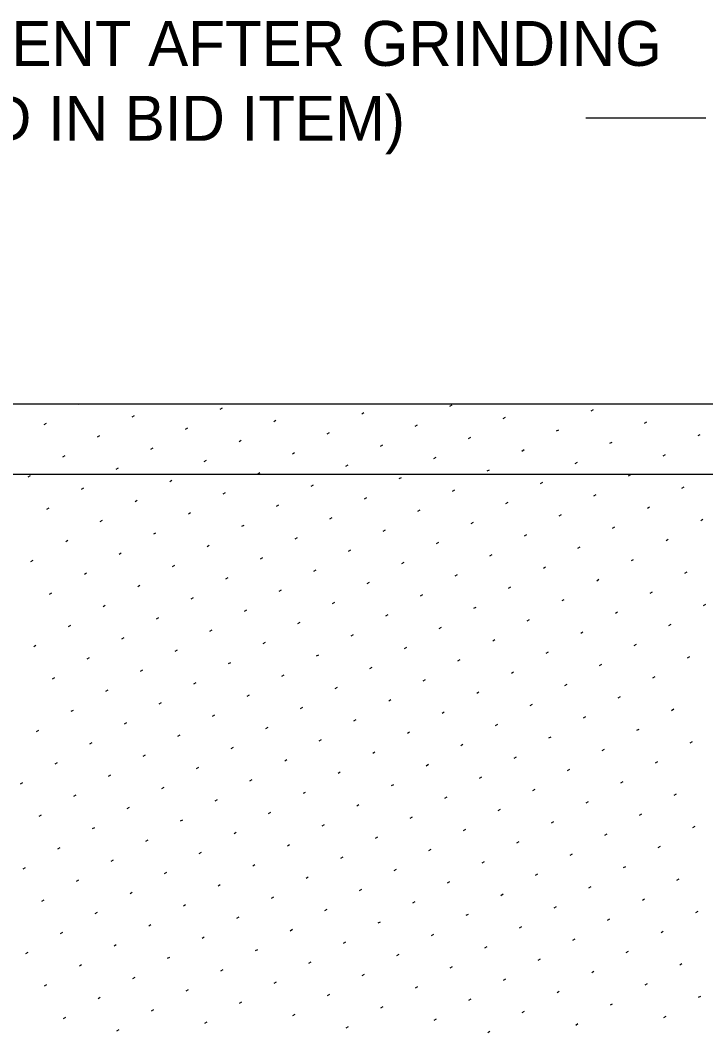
# Model space of a CAD drawing. Extents: x 49991.4 to 50021, y 49987.6 to 50011.4.
# Drawn here: x 50003.173 to 50004.089, y 49994.036 to 49995.39 of the extents above; entities that cross this region are included whole.
import ezdxf

# ---------------------------------------------------------------- set-up
doc = ezdxf.new("R2010")
doc.units = 0
for name, color, linetype in [('Level 1', 7, 'Continuous'), ('Level 2', 7, 'Continuous'), ('Level 3', 7, 'Continuous')]:
    doc.layers.add(name, color=color, linetype=linetype)

msp = doc.modelspace()

# ---------------------------------------------------------------- linework, layer by layer
at = {"layer": 'Level 1'}
for p, q in [((50002.5376, 49994.8772), (50004.5362, 49994.8772)), ((50008.0315, 49994.7828), (50001.9803, 49994.7828))]:
    msp.add_line(p, q, dxfattribs=at)
msp.add_ellipse((50004.6259, 49996.2377), major_axis=(0, -2.952), ratio=0.83118, start_param=5.208402, end_param=6.283185, dxfattribs=at)
at = {"layer": 'Level 3'}
for p, q in [((50004.0891, 49995.2588), (50003.9291, 49995.2588)), ((50003.2514, 49994.8768), (50003.2521, 49994.8772)), ((50003.4404, 49994.8704), (50003.4434, 49994.8722)), ((50003.6294, 49994.8641), (50003.6324, 49994.8658)), ((50003.7471, 49994.8743), (50003.7501, 49994.876)), ((50003.9361, 49994.868), (50003.9391, 49994.8697)), ((50003.205, 49994.85), (50003.208, 49994.8518)), ((50003.3227, 49994.8602), (50003.3257, 49994.862)), ((50003.5117, 49994.8539), (50003.5147, 49994.8556)), ((50003.8184, 49994.8577), (50003.8214, 49994.8595)), ((50004.0074, 49994.8514), (50004.0104, 49994.8532)), ((50003.394, 49994.8437), (50003.3971, 49994.8454)), ((50003.583, 49994.8373), (50003.5861, 49994.8391)), ((50003.7007, 49994.8475), (50003.7038, 49994.8493)), ((50003.8897, 49994.8412), (50003.8928, 49994.8429)), ((50004.0788, 49994.8349), (50004.0818, 49994.8366)), ((50003.2764, 49994.8335), (50003.2794, 49994.8352)), ((50003.4654, 49994.8271), (50003.4684, 49994.8289)), ((50003.7721, 49994.831), (50003.7751, 49994.8327)), ((50003.9611, 49994.8247), (50003.9641, 49994.8264)), ((50003.3477, 49994.8169), (50003.3507, 49994.8187)), ((50003.5367, 49994.8106), (50003.5397, 49994.8123)), ((50003.6544, 49994.8208), (50003.6574, 49994.8225)), ((50003.8434, 49994.8144), (50003.8464, 49994.8162)), ((50004.0324, 49994.8081), (50004.0354, 49994.8099)), ((50003.23, 49994.8067), (50003.233, 49994.8085)), ((50003.419, 49994.8004), (50003.4221, 49994.8021)), ((50003.608, 49994.794), (50003.6111, 49994.7958)), ((50003.7257, 49994.8042), (50003.7288, 49994.806)), ((50003.9147, 49994.7979), (50003.9178, 49994.7996)), ((50003.3014, 49994.7902), (50003.3044, 49994.7919)), ((50003.4904, 49994.7838), (50003.4934, 49994.7856)), ((50003.7971, 49994.7877), (50003.8001, 49994.7894)), ((50003.9861, 49994.7814), (50003.9891, 49994.7831)), ((50003.1837, 49994.78), (50003.1867, 49994.7817)), ((50003.3727, 49994.7736), (50003.3757, 49994.7754)), ((50003.5617, 49994.7673), (50003.5647, 49994.769)), ((50003.6794, 49994.7775), (50003.6824, 49994.7792)), ((50003.8684, 49994.7711), (50003.8714, 49994.7729)), ((50003.255, 49994.7634), (50003.258, 49994.7652)), ((50003.444, 49994.7571), (50003.4471, 49994.7588)), ((50003.7507, 49994.7609), (50003.7538, 49994.7627)), ((50003.9397, 49994.7546), (50003.9428, 49994.7563)), ((50004.0574, 49994.7648), (50004.0604, 49994.7666)), ((50003.3264, 49994.7469), (50003.3294, 49994.7486)), ((50003.5154, 49994.7405), (50003.5184, 49994.7423)), ((50003.633, 49994.7507), (50003.6361, 49994.7525)), ((50003.8221, 49994.7444), (50003.8251, 49994.7461)), ((50003.2087, 49994.7367), (50003.2117, 49994.7384)), ((50003.3977, 49994.7303), (50003.4007, 49994.7321)), ((50003.7044, 49994.7342), (50003.7074, 49994.7359)), ((50003.8934, 49994.7278), (50003.8964, 49994.7296)), ((50004.0111, 49994.738), (50004.0141, 49994.7398)), ((50003.28, 49994.7201), (50003.283, 49994.7219)), ((50003.469, 49994.7138), (50003.4721, 49994.7155)), ((50003.5867, 49994.724), (50003.5897, 49994.7257)), ((50003.7757, 49994.7176), (50003.7788, 49994.7194)), ((50004.0824, 49994.7215), (50004.0854, 49994.7233)), ((50003.3514, 49994.7036), (50003.3544, 49994.7053)), ((50003.658, 49994.7074), (50003.6611, 49994.7092)), ((50003.8471, 49994.7011), (50003.8501, 49994.7028)), ((50003.9647, 49994.7113), (50003.9678, 49994.713)), ((50003.2337, 49994.6934), (50003.2367, 49994.6951)), ((50003.4227, 49994.687), (50003.4257, 49994.6888)), ((50003.5404, 49994.6972), (50003.5434, 49994.699)), ((50003.7294, 49994.6909), (50003.7324, 49994.6926)), ((50004.0361, 49994.6947), (50004.0391, 49994.6965)), ((50003.305, 49994.6768), (50003.308, 49994.6786)), ((50003.6117, 49994.6807), (50003.6147, 49994.6824)), ((50003.8007, 49994.6743), (50003.8038, 49994.6761)), ((50003.9184, 49994.6845), (50003.9214, 49994.6863)), ((50003.1873, 49994.6666), (50003.1904, 49994.6684)), ((50003.3764, 49994.6603), (50003.3794, 49994.662)), ((50003.494, 49994.6705), (50003.4971, 49994.6722)), ((50003.683, 49994.6641), (50003.6861, 49994.6659)), ((50003.9897, 49994.668), (50003.9928, 49994.6697)), ((50003.2587, 49994.6501), (50003.2617, 49994.6518)), ((50003.5654, 49994.6539), (50003.5684, 49994.6557)), ((50003.7544, 49994.6476), (50003.7574, 49994.6493)), ((50003.8721, 49994.6578), (50003.8751, 49994.6595)), ((50004.0611, 49994.6514), (50004.0641, 49994.6532)), ((50003.33, 49994.6335), (50003.333, 49994.6353)), ((50003.4477, 49994.6437), (50003.4507, 49994.6455)), ((50003.6367, 49994.6374), (50003.6397, 49994.6391)), ((50003.9434, 49994.6412), (50003.9464, 49994.643)), ((50003.2123, 49994.6233), (50003.2154, 49994.6251)), ((50003.519, 49994.6272), (50003.5221, 49994.6289)), ((50003.708, 49994.6208), (50003.7111, 49994.6226)), ((50003.8257, 49994.631), (50003.8288, 49994.6328)), ((50004.0147, 49994.6247), (50004.0178, 49994.6264)), ((50003.2837, 49994.6068), (50003.2867, 49994.6085)), ((50003.4014, 49994.617), (50003.4044, 49994.6187)), ((50003.5904, 49994.6106), (50003.5934, 49994.6124)), ((50003.8971, 49994.6145), (50003.9001, 49994.6162)), ((50004.0861, 49994.6081), (50004.0891, 49994.6099)), ((50003.4727, 49994.6004), (50003.4757, 49994.6022)), ((50003.6617, 49994.5941), (50003.6647, 49994.5958)), ((50003.7794, 49994.6043), (50003.7824, 49994.606)), ((50003.9684, 49994.5979), (50003.9714, 49994.5997)), ((50003.2373, 49994.58), (50003.2404, 49994.5818)), ((50003.355, 49994.5902), (50003.358, 49994.592)), ((50003.544, 49994.5839), (50003.5471, 49994.5856)), ((50003.733, 49994.5775), (50003.7361, 49994.5793)), ((50003.8507, 49994.5877), (50003.8538, 49994.5895)), ((50004.0397, 49994.5814), (50004.0428, 49994.5831)), ((50003.4264, 49994.5737), (50003.4294, 49994.5754)), ((50003.6154, 49994.5673), (50003.6184, 49994.5691)), ((50003.9221, 49994.5712), (50003.9251, 49994.5729)), ((50003.191, 49994.5533), (50003.194, 49994.555)), ((50003.3087, 49994.5635), (50003.3117, 49994.5652)), ((50003.4977, 49994.5571), (50003.5007, 49994.5589)), ((50003.6867, 49994.5508), (50003.6897, 49994.5525)), ((50003.8044, 49994.561), (50003.8074, 49994.5627)), ((50003.9934, 49994.5546), (50003.9964, 49994.5564)), ((50003.2623, 49994.5367), (50003.2654, 49994.5385)), ((50003.38, 49994.5469), (50003.383, 49994.5487)), ((50003.569, 49994.5406), (50003.5721, 49994.5423)), ((50003.8757, 49994.5444), (50003.8788, 49994.5462)), ((50004.0647, 49994.5381), (50004.0678, 49994.5398)), ((50003.4514, 49994.5304), (50003.4544, 49994.5321)), ((50003.6404, 49994.524), (50003.6434, 49994.5258)), ((50003.758, 49994.5342), (50003.7611, 49994.536)), ((50003.9471, 49994.5279), (50003.9501, 49994.5296)), ((50003.216, 49994.51), (50003.219, 49994.5117)), ((50003.3337, 49994.5202), (50003.3367, 49994.5219)), ((50003.5227, 49994.5138), (50003.5257, 49994.5156)), ((50003.8294, 49994.5177), (50003.8324, 49994.5194)), ((50004.0184, 49994.5113), (50004.0214, 49994.5131)), ((50003.405, 49994.5036), (50003.408, 49994.5054)), ((50003.594, 49994.4973), (50003.5971, 49994.499)), ((50003.7117, 49994.5075), (50003.7147, 49994.5092)), ((50003.9007, 49994.5011), (50003.9038, 49994.5029)), ((50003.2873, 49994.4934), (50003.2904, 49994.4952)), ((50003.4764, 49994.4871), (50003.4794, 49994.4888)), ((50003.783, 49994.4909), (50003.7861, 49994.4927)), ((50003.9721, 49994.4846), (50003.9751, 49994.4863)), ((50003.3587, 49994.4769), (50003.3617, 49994.4786)), ((50003.5477, 49994.4705), (50003.5507, 49994.4723)), ((50003.6654, 49994.4807), (50003.6684, 49994.4825)), ((50003.8544, 49994.4744), (50003.8574, 49994.4761)), ((50003.241, 49994.4667), (50003.244, 49994.4684)), ((50003.43, 49994.4603), (50003.433, 49994.4621)), ((50003.7367, 49994.4642), (50003.7397, 49994.4659)), ((50003.9257, 49994.4578), (50003.9288, 49994.4596)), ((50004.0434, 49994.468), (50004.0464, 49994.4698)), ((50003.3123, 49994.4501), (50003.3154, 49994.4519)), ((50003.5014, 49994.4438), (50003.5044, 49994.4455)), ((50003.619, 49994.454), (50003.6221, 49994.4557)), ((50003.808, 49994.4476), (50003.8111, 49994.4494)), ((50003.1947, 49994.4399), (50003.1977, 49994.4416)), ((50003.3837, 49994.4336), (50003.3867, 49994.4353)), ((50003.6904, 49994.4374), (50003.6934, 49994.4392)), ((50003.8794, 49994.4311), (50003.8824, 49994.4328)), ((50003.9971, 49994.4413), (50004.0001, 49994.443)), ((50003.266, 49994.4233), (50003.269, 49994.4251)), ((50003.455, 49994.417), (50003.458, 49994.4188)), ((50003.5727, 49994.4272), (50003.5757, 49994.429)), ((50003.7617, 49994.4209), (50003.7647, 49994.4226)), ((50004.0684, 49994.4247), (50004.0714, 49994.4265)), ((50003.3373, 49994.4068), (50003.3404, 49994.4086)), ((50003.644, 49994.4107), (50003.6471, 49994.4124)), ((50003.833, 49994.4043), (50003.8361, 49994.4061)), ((50003.9507, 49994.4145), (50003.9538, 49994.4163)), ((50003.2197, 49994.3966), (50003.2227, 49994.3983)), ((50003.4087, 49994.3903), (50003.4117, 49994.392)), ((50003.5264, 49994.4005), (50003.5294, 49994.4022)), ((50003.7154, 49994.3941), (50003.7184, 49994.3959)), ((50004.0221, 49994.398), (50004.0251, 49994.3997)), ((50003.291, 49994.38), (50003.294, 49994.3818)), ((50003.5977, 49994.3839), (50003.6007, 49994.3857)), ((50003.7867, 49994.3776), (50003.7897, 49994.3793)), ((50003.9044, 49994.3878), (50003.9074, 49994.3895)), ((50003.1733, 49994.3698), (50003.1764, 49994.3716)), ((50003.3623, 49994.3635), (50003.3654, 49994.3653)), ((50003.48, 49994.3737), (50003.483, 49994.3755)), ((50003.669, 49994.3674), (50003.6721, 49994.3691)), ((50003.858, 49994.361), (50003.8611, 49994.3628)), ((50003.9757, 49994.3712), (50003.9788, 49994.373)), ((50003.2447, 49994.3533), (50003.2477, 49994.355)), ((50003.5514, 49994.3572), (50003.5544, 49994.3589)), ((50003.7404, 49994.3508), (50003.7434, 49994.3526)), ((50004.0471, 49994.3547), (50004.0501, 49994.3564)), ((50003.316, 49994.3367), (50003.319, 49994.3385)), ((50003.4337, 49994.347), (50003.4367, 49994.3487)), ((50003.6227, 49994.3406), (50003.6257, 49994.3424)), ((50003.8117, 49994.3343), (50003.8147, 49994.336)), ((50003.9294, 49994.3445), (50003.9324, 49994.3462)), ((50003.1983, 49994.3265), (50003.2014, 49994.3283)), ((50003.3873, 49994.3202), (50003.3904, 49994.3219)), ((50003.505, 49994.3304), (50003.508, 49994.3322)), ((50003.694, 49994.3241), (50003.6971, 49994.3258)), ((50004.0007, 49994.3279), (50004.0038, 49994.3297)), ((50003.2697, 49994.31), (50003.2727, 49994.3117)), ((50003.5764, 49994.3139), (50003.5794, 49994.3156)), ((50003.7654, 49994.3075), (50003.7684, 49994.3093)), ((50003.883, 49994.3177), (50003.8861, 49994.3195)), ((50004.0721, 49994.3114), (50004.0751, 49994.3131)), ((50003.341, 49994.2934), (50003.344, 49994.2952)), ((50003.4587, 49994.3037), (50003.4617, 49994.3054)), ((50003.6477, 49994.2973), (50003.6507, 49994.2991)), ((50003.9544, 49994.3012), (50003.9574, 49994.3029)), ((50003.2233, 49994.2832), (50003.2264, 49994.285)), ((50003.53, 49994.2871), (50003.533, 49994.2889)), ((50003.719, 49994.2808), (50003.7221, 49994.2825)), ((50003.8367, 49994.291), (50003.8397, 49994.2927)), ((50004.0257, 49994.2846), (50004.0288, 49994.2864)), ((50003.2947, 49994.2667), (50003.2977, 49994.2684)), ((50003.4123, 49994.2769), (50003.4154, 49994.2786)), ((50003.6014, 49994.2706), (50003.6044, 49994.2723)), ((50003.908, 49994.2744), (50003.9111, 49994.2762)), ((50003.177, 49994.2565), (50003.18, 49994.2582)), ((50003.4837, 49994.2603), (50003.4867, 49994.2621)), ((50003.6727, 49994.254), (50003.6757, 49994.2558)), ((50003.7904, 49994.2642), (50003.7934, 49994.266)), ((50003.9794, 49994.2579), (50003.9824, 49994.2596)), ((50003.2483, 49994.2399), (50003.2514, 49994.2417)), ((50003.366, 49994.2501), (50003.369, 49994.2519)), ((50003.555, 49994.2438), (50003.558, 49994.2456)), ((50003.8617, 49994.2477), (50003.8647, 49994.2494)), ((50004.0507, 49994.2413), (50004.0538, 49994.2431)), ((50003.4373, 49994.2336), (50003.4404, 49994.2353)), ((50003.6264, 49994.2273), (50003.6294, 49994.229)), ((50003.744, 49994.2375), (50003.7471, 49994.2392)), ((50003.933, 49994.2311), (50003.9361, 49994.2329)), ((50003.202, 49994.2132), (50003.205, 49994.2149)), ((50003.3197, 49994.2234), (50003.3227, 49994.2251)), ((50003.5087, 49994.217), (50003.5117, 49994.2188)), ((50003.8154, 49994.2209), (50003.8184, 49994.2227)), ((50004.0044, 49994.2146), (50004.0074, 49994.2163)), ((50003.391, 49994.2068), (50003.394, 49994.2086)), ((50003.58, 49994.2005), (50003.583, 49994.2023)), ((50003.6977, 49994.2107), (50003.7007, 49994.2125)), ((50003.8867, 49994.2044), (50003.8897, 49994.2061)), ((50003.2733, 49994.1966), (50003.2764, 49994.1984)), ((50003.4623, 49994.1903), (50003.4654, 49994.192)), ((50003.769, 49994.1942), (50003.7721, 49994.1959)), ((50003.958, 49994.1878), (50003.9611, 49994.1896)), ((50004.0757, 49994.198), (50004.0788, 49994.1998)), ((50003.3447, 49994.1801), (50003.3477, 49994.1818)), ((50003.5337, 49994.1737), (50003.5367, 49994.1755)), ((50003.6514, 49994.184), (50003.6544, 49994.1857)), ((50003.8404, 49994.1776), (50003.8434, 49994.1794)), ((50004.0294, 49994.1713), (50004.0324, 49994.173)), ((50003.227, 49994.1699), (50003.23, 49994.1716)), ((50003.416, 49994.1635), (50003.419, 49994.1653)), ((50003.7227, 49994.1674), (50003.7257, 49994.1692)), ((50003.9117, 49994.1611), (50003.9147, 49994.1628)), ((50003.2983, 49994.1533), (50003.3014, 49994.1551)), ((50003.4873, 49994.147), (50003.4904, 49994.1487)), ((50003.605, 49994.1572), (50003.608, 49994.1589)), ((50003.794, 49994.1509), (50003.7971, 49994.1526)), ((50003.983, 49994.1445), (50003.9861, 49994.1463)), ((50003.1806, 49994.1431), (50003.1837, 49994.1449)), ((50003.3697, 49994.1368), (50003.3727, 49994.1385)), ((50003.6764, 49994.1407), (50003.6794, 49994.1424)), ((50003.8654, 49994.1343), (50003.8684, 49994.1361)), ((50003.252, 49994.1266), (50003.255, 49994.1283)), ((50003.441, 49994.1202), (50003.444, 49994.122)), ((50003.5587, 49994.1304), (50003.5617, 49994.1322)), ((50003.7477, 49994.1241), (50003.7507, 49994.1259)), ((50003.9367, 49994.1178), (50003.9397, 49994.1195)), ((50004.0544, 49994.128), (50004.0574, 49994.1297)), ((50003.3233, 49994.11), (50003.3264, 49994.1118)), ((50003.5123, 49994.1037), (50003.5154, 49994.1054)), ((50003.63, 49994.1139), (50003.633, 49994.1156)), ((50003.819, 49994.1076), (50003.8221, 49994.1093)), ((50003.2056, 49994.0998), (50003.2087, 49994.1016)), ((50003.3947, 49994.0935), (50003.3977, 49994.0952)), ((50003.7014, 49994.0974), (50003.7044, 49994.0991)), ((50003.8904, 49994.091), (50003.8934, 49994.0928)), ((50004.008, 49994.1012), (50004.0111, 49994.103)), ((50003.277, 49994.0833), (50003.28, 49994.085)), ((50003.466, 49994.0769), (50003.469, 49994.0787)), ((50003.5837, 49994.0871), (50003.5867, 49994.0889)), ((50003.7727, 49994.0808), (50003.7757, 49994.0826)), ((50004.0794, 49994.0847), (50004.0824, 49994.0864)), ((50003.3483, 49994.0667), (50003.3514, 49994.0685)), ((50003.655, 49994.0706), (50003.658, 49994.0723)), ((50003.844, 49994.0643), (50003.8471, 49994.066)), ((50003.9617, 49994.0745), (50003.9647, 49994.0762)), ((50003.2306, 49994.0565), (50003.2337, 49994.0583)), ((50003.4197, 49994.0502), (50003.4227, 49994.0519)), ((50003.5373, 49994.0604), (50003.5404, 49994.0621)), ((50003.7264, 49994.054), (50003.7294, 49994.0558)), ((50004.033, 49994.0579), (50004.0361, 49994.0597)), ((50003.302, 49994.04), (50003.305, 49994.0417)), ((50003.6087, 49994.0438), (50003.6117, 49994.0456)), ((50003.7977, 49994.0375), (50003.8007, 49994.0393)), ((50003.9154, 49994.0477), (50003.9184, 49994.0495))]:
    msp.add_line(p, q, dxfattribs=at)

# ---------------------------------------------------------------- texts
at = {"layer": 'Level 2'}
for s, p in [('TOP OF PAVEMENT AFTER GRINDING', (50002.5594, 49995.3288)), ('(NOT INCLUDED IN BID ITEM)', (50002.5594, 49995.2288))]:
    msp.add_text(s, height=0.06, dxfattribs=at).set_placement(p)

doc.saveas('drawing.dxf')
